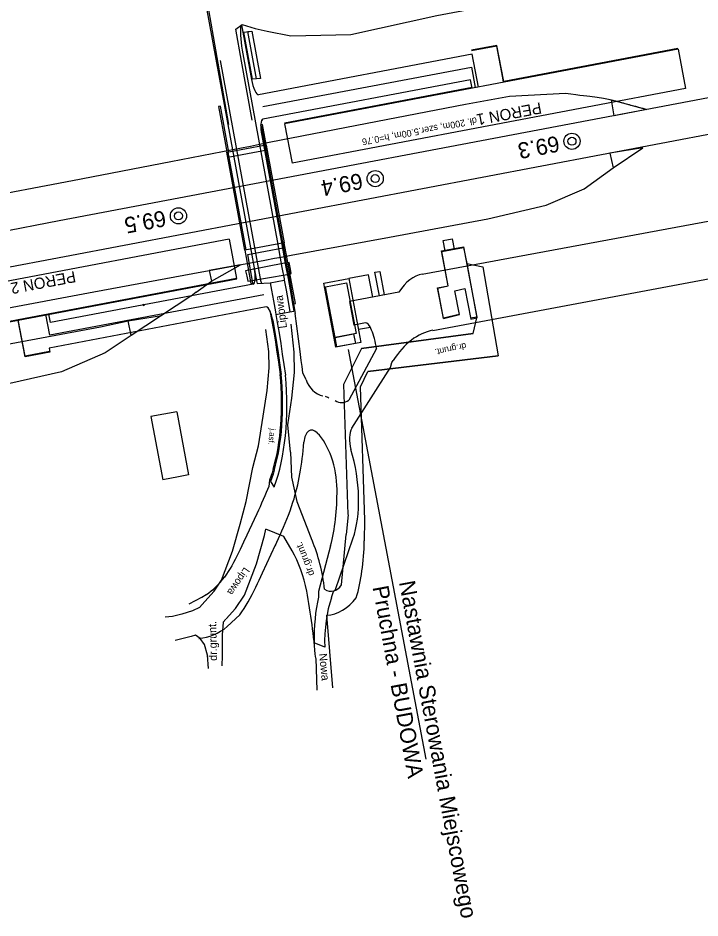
# Model space of a CAD drawing. Extents: x 6541740 to 6566395, y 5525066 to 5530361.
# Drawn here: x 6555216.3 to 6555301.5, y 5525704 to 5525816.3 of the extents above; entities that cross this region are included whole.
import ezdxf

# ---------------------------------------------------------------- set-up
doc = ezdxf.new("R2010")
doc.units = 0
for name, color, linetype in [('Domyślna', 7, 'Continuous'), ('ps_wymiarowanie', 7, 'Continuous'), ('TOR_PRZEK_P-komponent', 7, 'Continuous'), ('TOR_PRZEK_P-pomoc', 7, 'Continuous'), ('TOR_PS_OPIS_T-symbole geometrii', 7, 'Continuous'), ('TOR_PS_T-rowy otwarte nieumocnione', 7, 'Continuous'), ('TOR_PS_T-wypelnienia', 7, 'Continuous'), ('TOR_RAMKI-ramka+tabelka 1', 7, 'Continuous'), ('TOR_W-warstwa dodatkowa 2', 7, 'Continuous')]:
    doc.layers.add(name, color=color, linetype=linetype)

# ---------------------------------------------------------------- blocks, each defined once
blk = doc.blocks.new('4010_1')
at = {"layer": 'Domyślna'}
for radius in [0.75, 0.375]:
    blk.add_circle((0, 0), radius, dxfattribs=at)

msp = doc.modelspace()

# ---------------------------------------------------------------- linework, layer by layer
at = {"layer": 'ps_wymiarowanie'}
for p, q in [((6555269.64, 5525787.23), (6555269.4, 5525788.5)), ((6555269.19, 5525787.23), (6555271.94, 5525787.72)), ((6555270, 5525782.87), (6555269.19, 5525787.23)), ((6555271.94, 5525787.72), (6555273.59, 5525778.94)), ((6555268.7, 5525782.61), (6555270, 5525782.87)), ((6555269.42, 5525778.84), (6555268.7, 5525782.61)), ((6555269.43, 5525778.8), (6555268.71, 5525782.57)), ((6555271.38, 5525779.28), (6555269.42, 5525778.84)), ((6555273.59, 5525778.94), (6555272.81, 5525778.81)), ((6555236.12, 5525767.14), (6555232.91, 5525766.55)), ((6555236.12, 5525767.14), (6555237.61, 5525759.25)), ((6555232.91, 5525766.55), (6555234.41, 5525758.66))]:
    msp.add_line(p, q, dxfattribs=at)
msp.add_lwpolyline([(6555269.64, 5525787.23), (6555269.4, 5525788.5), (6555270.51, 5525788.71), (6555270.75, 5525787.44)], close=True, dxfattribs=at)
for points in [[(6555268.71, 5525782.57), (6555270.03, 5525782.87), (6555269.21, 5525787.15)], [(6555269.21, 5525787.15), (6555271.94, 5525787.66), (6555272.34, 5525785.65), (6555273.6, 5525778.86)], [(6555269.43, 5525778.8), (6555271.41, 5525779.26), (6555270.84, 5525782.24), (6555272.11, 5525782.53), (6555272.85, 5525778.68), (6555273.6, 5525778.86)], [(6555237.61, 5525759.25), (6555236.36, 5525759), (6555234.41, 5525758.66)]]:
    msp.add_lwpolyline(points, dxfattribs=at)
at = {"layer": 'TOR_PRZEK_P-komponent'}
for p, q in [((6555381.82, 5525821.35), (6555221.45, 5525790.95)), ((6555362.21, 5525813.05), (6555222.13, 5525786.49)), ((6555221.45, 5525790.95), (6555010.48, 5525750.96)), ((6555222.13, 5525786.49), (6554997.05, 5525743.82))]:
    msp.add_line(p, q, dxfattribs=at)
at = {"layer": 'TOR_PRZEK_P-pomoc'}
for p, q in [((6555298.72, 5525812.39), (6555249.59, 5525803.08)), ((6555298.7, 5525812.47), (6555276.95, 5525808.34)), ((6555298.72, 5525812.39), (6555299.65, 5525807.48)), ((6555273.01, 5525807.6), (6555249.58, 5525803.16)), ((6555299.65, 5525807.48), (6555250.52, 5525798.16)), ((6555249.59, 5525803.08), (6555250.52, 5525798.16)), ((6555242.67, 5525788.69), (6555193.54, 5525779.37)), ((6555242.67, 5525788.69), (6555243.6, 5525783.77)), ((6555243.62, 5525783.69), (6555216.34, 5525778.53)), ((6555243.6, 5525783.77), (6555216.35, 5525778.61)), ((6555216.35, 5525778.61), (6555194.48, 5525774.46)), ((6555216.34, 5525778.53), (6555194.49, 5525774.38))]:
    msp.add_line(p, q, dxfattribs=at)
at = {"layer": 'TOR_PS_OPIS_T-symbole geometrii'}
for p, q in [((6555244.22, 5525815.42), (6555245.46, 5525808.62)), ((6555244.37, 5525811.8), (6555248.74, 5525788.01)), ((6555241.55, 5525811), (6555245.84, 5525787.66)), ((6555246.66, 5525802.8), (6555249.36, 5525788.07)), ((6555246.75, 5525801.63), (6555249.24, 5525788.06)), ((6555266.79, 5525784.32), (6555310.58, 5525792.41)), ((6555268.12, 5525777.3), (6555307.72, 5525784.7)), ((6555247.81, 5525783.23), (6555249.55, 5525783.55)), ((6555246.15, 5525783.16), (6555247.81, 5525783.23)), ((6555263.87, 5525782.08), (6555257.69, 5525780.9)), ((6555257.69, 5525780.9), (6555258.25, 5525777.94)), ((6555248.5, 5525779.29), (6555250.25, 5525779.61)), ((6555250.25, 5525779.61), (6555250.74, 5525779.7)), ((6555259.71, 5525778.23), (6555258.25, 5525777.95)), ((6555262.98, 5525773.27), (6555263.15, 5525773.53)), ((6555257.99, 5525765.08), (6555262.81, 5525772.65)), ((6555262.81, 5525772.65), (6555262.98, 5525773.27)), ((6555247.72, 5525758.6), (6555247.61, 5525757.8)), ((6555247.84, 5525758.43), (6555248.3, 5525757.75)), ((6555246.11, 5525754.4), (6555244.55, 5525751.04)), ((6555255.96, 5525744.97), (6555258.13, 5525751.28)), ((6555255.32, 5525750.41), (6555253.82, 5525744.7)), ((6555239.27, 5525743.98), (6555239.82, 5525744.35)), ((6555253.82, 5525744.7), (6555253.82, 5525744.03)), ((6555255.43, 5525743.94), (6555255.7, 5525744.71)), ((6555255.7, 5525744.71), (6555255.96, 5525744.97)), ((6555239.22, 5525743.95), (6555237.62, 5525743.11)), ((6555244, 5525741.78), (6555242.44, 5525740.33)), ((6555254.6, 5525737.74), (6555253.28, 5525738.31))]:
    msp.add_line(p, q, dxfattribs=at)
for points in [[(6555232.86, 5525855.52), (6555232.99, 5525854.81), (6555233.25, 5525853.4), (6555233.51, 5525852), (6555233.51, 5525852), (6555241.02, 5525811.14), (6555245.34, 5525787.61)], [(6555249.25, 5525788.01), (6555249.5, 5525786.61), (6555249.76, 5525785.2), (6555250.02, 5525783.77), (6555250.28, 5525782.34), (6555250.54, 5525780.88), (6555250.74, 5525779.7)], [(6555249.37, 5525788.02), (6555249.63, 5525786.62), (6555249.89, 5525785.21), (6555250.15, 5525783.78), (6555250.41, 5525782.34), (6555250.67, 5525780.88), (6555250.92, 5525779.41)], [(6555245.34, 5525787.61), (6555245.59, 5525786.23), (6555245.85, 5525784.85), (6555246.09, 5525783.49), (6555246.15, 5525783.16)], [(6555245.84, 5525787.66), (6555246.09, 5525786.27), (6555246.35, 5525784.89), (6555246.6, 5525783.52), (6555246.72, 5525783.18)], [(6555248.75, 5525787.96), (6555249, 5525786.57), (6555249.26, 5525785.16), (6555249.52, 5525783.75), (6555249.55, 5525783.55)], [(6555249.55, 5525783.55), (6555249.77, 5525782.32), (6555250.03, 5525780.89), (6555250.25, 5525779.61)], [(6555247.81, 5525783.23), (6555247.97, 5525782.33), (6555248.21, 5525780.98), (6555248.45, 5525779.63), (6555248.5, 5525779.29)], [(6555247.73, 5525779.77), (6555248.13, 5525777.73), (6555248.24, 5525777.08), (6555248.44, 5525775.81), (6555248.64, 5525774.56), (6555248.83, 5525773.32), (6555249.05, 5525771.81)], [(6555248.5, 5525779.29), (6555248.67, 5525778.29), (6555248.9, 5525776.96), (6555249.11, 5525775.64), (6555249.31, 5525774.33), (6555249.51, 5525773.03), (6555249.7, 5525771.69)], [(6555252.27, 5525771.14), (6555251.85, 5525772.01), (6555251.77, 5525772.77), (6555251.68, 5525773.53), (6555251.58, 5525774.28), (6555251.52, 5525774.65), (6555250.92, 5525779.41)], [(6555248.12, 5525778.55), (6555248.37, 5525777.06), (6555248.58, 5525775.78), (6555248.78, 5525774.51), (6555248.96, 5525773.26), (6555249.18, 5525771.79)], [(6555261.08, 5525775.03), (6555257.6, 5525768.59)], [(6555248.18, 5525760.02), (6555248.03, 5525759.52), (6555247.88, 5525759.06), (6555247.72, 5525758.6)], [(6555248.3, 5525759.86), (6555248.15, 5525759.36), (6555248, 5525758.89), (6555247.84, 5525758.43)], [(6555247.61, 5525757.8), (6555247.31, 5525757.07), (6555247.12, 5525756.63), (6555246.93, 5525756.18), (6555246.73, 5525755.74), (6555246.53, 5525755.29), (6555246.32, 5525754.85), (6555246.11, 5525754.4)], [(6555244, 5525741.78), (6555244.27, 5525742.16), (6555244.54, 5525742.57), (6555244.8, 5525743), (6555245.05, 5525743.43), (6555245.3, 5525743.87), (6555245.54, 5525744.32), (6555245.77, 5525744.77), (6555245.99, 5525745.23), (6555246.21, 5525745.69), (6555246.43, 5525746.14), (6555246.64, 5525746.6), (6555246.85, 5525747.05), (6555246.85, 5525747.05), (6555248.46, 5525750.52), (6555248.41, 5525750.41), (6555248.62, 5525750.86), (6555248.84, 5525751.32), (6555249.05, 5525751.78), (6555249.26, 5525752.26), (6555249.47, 5525752.74), (6555249.68, 5525753.23), (6555249.88, 5525753.74), (6555250.08, 5525754.25), (6555250.28, 5525754.78), (6555250.47, 5525755.33), (6555250.64, 5525755.86)], [(6555244.68, 5525751.31), (6555244.47, 5525750.86), (6555244.26, 5525750.41), (6555244.05, 5525749.97), (6555243.84, 5525749.54), (6555243.64, 5525749.12), (6555243.43, 5525748.71), (6555243.21, 5525748.32), (6555243, 5525747.93), (6555242.78, 5525747.56), (6555242.56, 5525747.2), (6555242.34, 5525746.86), (6555242.1, 5525746.51)]]:
    msp.add_lwpolyline(points, dxfattribs=at)
for centre, major_axis, ratio, start_param, end_param in [((6555245.62, 5525811.92), (-0.93, 4.91), 0.25, 0.758321, 1.548465), ((6555245.96, 5525808.67), (0.37, -1.97), 0.25, 4.690058, 6.279955), ((6555247.24, 5525801.68), (-0.37, 1.97), 0.25, 6.279955, 7.831651), ((6555276.55, 5525732.74), (-9.78, 51.58), 0.25, 6.281998, 6.535305), ((6555247.67, 5525778.26), (-0.37, 1.97), 0.25, 4.81114, 6.283185), ((6555260.27, 5525775.28), (-0.56, 2.95), 0.25, 4.578281, 6.283592), ((6555272.54, 5525753.97), (-4.44, 23.33), 0.499999, 6.281393, 6.771299), ((6555237.67, 5525773.93), (-4.11, 21.59), 0.499999, 3.919278, 4.519453), ((6555237.67, 5525773.93), (-4.16, 21.83), 0.499999, 3.919278, 4.519453), ((6555237.67, 5525773.93), (-4.35, 22.81), 0.499999, 3.83349, 4.519453), ((6555254.88, 5525772.13), (-0.58, 3.05), 0.897189, 1.728216, 2.750899), ((6555254.48, 5525767.93), (-0.21, 1.1), 0.976601, 5.483546, 5.892492), ((6555256.72, 5525769.68), (-0.26, 1.38), 0.999987, 2.341953, 3.629706), ((6555253.32, 5525762.37), (-0.47, 2.46), 0.499999, 5.655689, 7.358003), ((6555252.79, 5525759.07), (-1.19, 6.26), 0.499999, 4.357266, 5.655689), ((6555258.93, 5525763.12), (-0.44, 2.33), 0.499999, 0.488113, 1.775866), ((6555237.67, 5525773.93), (-5.15, 27.04), 0.499999, 3.889479, 4.21641), ((6555252.79, 5525759.07), (-2.15, 11.3), 0.499999, 3.861049, 4.917459), ((6555245.76, 5525762.47), (-3.7, 19.4), 0.499999, 3.950241, 4.357266), ((6555233.72, 5525765.42), (-4.16, 21.83), 0.499999, 3.327431, 3.579278), ((6555261.82, 5525734.62), (-3.04, 15.96), 0.499999, 0.849414, 1.244004), ((6555261.82, 5525734.62), (-2.57, 13.51), 0.499999, 0.719457, 1.244004), ((6555234.67, 5525763.97), (4.77, -25.05), 0.499999, 6.240346, 6.537831)]:
    msp.add_ellipse(centre, major_axis=major_axis, ratio=ratio, start_param=start_param, end_param=end_param, dxfattribs=at)
at = {"layer": 'TOR_PS_T-rowy otwarte nieumocnione'}
for p, q in [((6555223.1, 5525796), (6555235.39, 5525798.36)), ((6555238.12, 5525784.38), (6555240.17, 5525784.76)), ((6555225.78, 5525782.1), (6555238.12, 5525784.38)), ((6555230.06, 5525778.47), (6555234.23, 5525779.15))]:
    msp.add_line(p, q, dxfattribs=at)
for points in [[(6555259.91, 5525803.17), (6555272.18, 5525805.55), (6555277.67, 5525806.54), (6555284.68, 5525806.91)], [(6555235.39, 5525798.36), (6555244.42, 5525800.13), (6555245.32, 5525800.3), (6555246.46, 5525800.54), (6555247.67, 5525800.77), (6555259.91, 5525803.17)], [(6555286.98, 5525794.96), (6555290.63, 5525797.58)], [(6555186.25, 5525789), (6555198.53, 5525791.32), (6555210.81, 5525793.69), (6555223.1, 5525796)], [(6555274.96, 5525791.23), (6555282.27, 5525792.91), (6555286.98, 5525794.96)], [(6555248.33, 5525786.3), (6555249.17, 5525786.45), (6555250.41, 5525786.68), (6555262.7, 5525788.95), (6555274.96, 5525791.23)], [(6555240.17, 5525784.76), (6555247.11, 5525786.06), (6555248.33, 5525786.3)], [(6555238.56, 5525782.05), (6555240.48, 5525783.43)], [(6555201.23, 5525777.46), (6555213.53, 5525779.81), (6555225.78, 5525782.1)], [(6555237.91, 5525781.58), (6555237.9, 5525781.58), (6555230.44, 5525776.64)], [(6555238.56, 5525782.05), (6555237.91, 5525781.58)], [(6555226.59, 5525777.74), (6555230.06, 5525778.47)], [(6555189.79, 5525770.76), (6555202.07, 5525773.1), (6555214.35, 5525775.45), (6555226.59, 5525777.73)], [(6555230.44, 5525776.64), (6555227.19, 5525774.5)], [(6555227.19, 5525774.5), (6555221.73, 5525772.13), (6555215.27, 5525770.65)]]:
    msp.add_lwpolyline(points, dxfattribs=at)
for points in [[(6555294.82, 5525804.88), (6555290.75, 5525804.08), (6555290.4, 5525806.06)], [(6555294.31, 5525800.08), (6555290.21, 5525799.4), (6555290.63, 5525797.58)], [(6555244.08, 5525785.49), (6555240.17, 5525784.76), (6555240.48, 5525783.43)], [(6555234.23, 5525779.15), (6555230.44, 5525776.64), (6555230.06, 5525778.47)]]:
    msp.add_lwpolyline(points, close=True, dxfattribs=at)
msp.add_open_spline([(6555284.68, 5525806.91), (6555286.58, 5525806.63), (6555288.47, 5525806.46), (6555290.4, 5525806.06), (6555291.13, 5525805.91), (6555291.87, 5525805.67), (6555292.61, 5525805.47), (6555293.35, 5525805.28), (6555294.09, 5525805.08), (6555294.82, 5525804.88)], degree=3, dxfattribs=at)
at = {"layer": 'TOR_PS_T-wypelnienia'}
for p, q in [((6555257.51, 5525754.28), (6555257.28, 5525751.84)), ((6555259.55, 5525751.02), (6555259.6, 5525753.59)), ((6555256.69, 5525745.56), (6555257.28, 5525751.84)), ((6555255.62, 5525732.67), (6555254.85, 5525741.75)), ((6555253.48, 5525736.36), (6555253.6, 5525732.4))]:
    msp.add_line(p, q, dxfattribs=at)
for points in [[(6555242.64, 5525802.98), (6555241.29, 5525810.65), (6555239.54, 5525820.69), (6555236.84, 5525835.55), (6555235.45, 5525843.55)], [(6555245.93, 5525814.97), (6555247.4, 5525814.66), (6555250.39, 5525814.05), (6555257.86, 5525814.24), (6555268.58, 5525816.61), (6555283.95, 5525819.5), (6555297.12, 5525822.42), (6555318.23, 5525825.3), (6555325.99, 5525826.63)], [(6555243.52, 5525814.89), (6555244.3, 5525815.48), (6555245.93, 5525814.97)], [(6555245.55, 5525803.54), (6555244.21, 5525810.91), (6555243.52, 5525814.89)], [(6555272.34, 5525785.65), (6555274.36, 5525785.21), (6555276.24, 5525774.13), (6555259.98, 5525772.15)], [(6555250.32, 5525762.1), (6555250.01, 5525765.52), (6555250.51, 5525768.85), (6555250.82, 5525772.05), (6555250.77, 5525774.58), (6555250.42, 5525778.08)], [(6555259.2, 5525775.04), (6555273.14, 5525776.89), (6555273.6, 5525778.86)], [(6555239.65, 5525743.48), (6555240.78, 5525744.75), (6555241.73, 5525746.14), (6555243.11, 5525749.73), (6555244.05, 5525753.13), (6555244.78, 5525755.94), (6555245.63, 5525760.19), (6555246.35, 5525762.88), (6555246.92, 5525766.58), (6555247.4, 5525769.8), (6555247.67, 5525772.64), (6555247.63, 5525774.66), (6555247.24, 5525777.41)], [(6555273.14, 5525776.89), (6555259.2, 5525775.04), (6555256.94, 5525770.53), (6555257.49, 5525754.3)], [(6555259.6, 5525753.59), (6555259.05, 5525770.25), (6555259.98, 5525772.15), (6555276.24, 5525774.13)], [(6555250.32, 5525762.1), (6555250.45, 5525758.97), (6555251.14, 5525755.95), (6555252.39, 5525752.72), (6555253.01, 5525751.1)], [(6555242.29, 5525741.28), (6555243.47, 5525742.6), (6555244.58, 5525744.23), (6555246.09, 5525748.15), (6555247.07, 5525751.7), (6555247.27, 5525752.48)], [(6555250.55, 5525749.79), (6555249.48, 5525751.59), (6555247.27, 5525752.48)], [(6555239.65, 5525743.48), (6555238.96, 5525742.73), (6555238.1, 5525742.3), (6555236.78, 5525741.89), (6555235.6, 5525741.6), (6555234.69, 5525741.52)], [(6555241.92, 5525740.87), (6555241.78, 5525739.29), (6555241.78, 5525736.67), (6555241.74, 5525735.41)], [(6555242.27, 5525741.26), (6555241.92, 5525740.87)], [(6555238.49, 5525739.26), (6555237.94, 5525739.09), (6555235.93, 5525738.6)], [(6555240.08, 5525735.1), (6555239.96, 5525736.76), (6555239.59, 5525738.1), (6555239.05, 5525738.86), (6555238.49, 5525739.26)]]:
    msp.add_lwpolyline(points, dxfattribs=at)
msp.add_lwpolyline([(6555249.96, 5525785.74), (6555249.59, 5525785.67), (6555244.7, 5525784.73), (6555244.87, 5525784.06), (6555245, 5525783.42), (6555249.93, 5525784.29), (6555250.43, 5525784.38), (6555250.32, 5525784.93), (6555250.16, 5525785.78)], close=True, dxfattribs=at)
for centre, major_axis, start_param, end_param in [((6555248.61, 5525745.6), (-2.18, 11.45), 4.564417, 5.116223), ((6555248.54, 5525757.26), (-3.92, 20.59), 3.916546, 4.310739), ((6555247.39, 5525743.45), (-1.92, 10.08), 4.747485, 5.293863), ((6555254.74, 5525749.54), (-0.91, 4.79), 2.71727, 3.641992), ((6555231.38, 5525741.24), (-7.96, 41.78), 4.50108, 4.701549), ((6555252.23, 5525758.51), (-3.18, 16.69), 3.075126, 3.562422)]:
    msp.add_ellipse(centre, major_axis=major_axis, ratio=0.499999, start_param=start_param, end_param=end_param, dxfattribs=at)
at = {"layer": 'TOR_W-warstwa dodatkowa 2'}
for p, q in [((6555249.39, 5525788.2), (6555247.15, 5525800.4)), ((6555249.57, 5525788.22), (6555247.32, 5525800.41)), ((6555244.62, 5525787.32), (6555242.38, 5525799.52)), ((6555244.8, 5525787.34), (6555242.56, 5525799.53)), ((6555260.06, 5525784.23), (6555257.6, 5525783.78)), ((6555260.61, 5525781.46), (6555260.06, 5525784.23)), ((6555217.2, 5525774.01), (6555216.34, 5525778.53)), ((6555217.21, 5525774.09), (6555216.35, 5525778.61)), ((6555260.3, 5525777.66), (6555258.81, 5525777.39)), ((6555220.28, 5525774.59), (6555217.2, 5525774.01)), ((6555220.26, 5525774.67), (6555217.21, 5525774.09)), ((6555257.53, 5525774.92), (6555267.23, 5525723.78))]:
    msp.add_line(p, q, dxfattribs=at)
for points in [[(6555246.58, 5525808.73), (6555245.59, 5525808.63), (6555244.5, 5525814.53), (6555245.5, 5525814.63)], [(6555246.58, 5525808.73), (6555246.09, 5525808.68), (6555245, 5525814.58), (6555245.5, 5525814.63)], [(6555260.88, 5525784.55), (6555261.47, 5525784.66), (6555262.02, 5525781.72), (6555261.43, 5525781.61)], [(6555254.49, 5525783.2), (6555257.6, 5525783.78), (6555259.11, 5525775.8), (6555256, 5525775.22)], [(6555258.52, 5525776.91), (6555255.9, 5525776.42), (6555254.7, 5525782.73), (6555257.33, 5525783.22)], [(6555255.9, 5525776.42), (6555258.21, 5525776.85), (6555258.44, 5525775.67), (6555256.12, 5525775.24)]]:
    msp.add_lwpolyline(points, close=True, dxfattribs=at)
for points in [[(6555276.95, 5525808.34), (6555276.09, 5525812.86), (6555272.91, 5525812.26)], [(6555276.83, 5525808.83), (6555276.09, 5525812.78), (6555272.93, 5525812.18)], [(6555273.79, 5525807.66), (6555273.01, 5525811.76), (6555246.33, 5525806.7)], [(6555246.89, 5525805.24), (6555272.92, 5525810.15), (6555273.4, 5525807.59)], [(6555273.02, 5525807.52), (6555272.82, 5525808.58), (6555246.87, 5525803.66)], [(6555276.94, 5525808.26), (6555276.83, 5525808.83)], [(6555247.06, 5525800.38), (6555242.64, 5525799.55), (6555241.6, 5525805.27), (6555241.35, 5525805.22), (6555242.49, 5525798.91), (6555247.43, 5525799.84), (6555246.85, 5525803.01), (6555246.6, 5525802.97), (6555246.6, 5525802.97), (6555247.06, 5525800.38)], [(6555245.64, 5525783.2), (6555245.64, 5525783.2), (6555245, 5525786.76), (6555249.42, 5525787.6), (6555250.68, 5525780.59), (6555250.94, 5525780.64), (6555249.56, 5525788.24), (6555244.63, 5525787.3), (6555245.38, 5525783.15), (6555245.64, 5525783.2)], [(6555245.69, 5525783.07), (6555220.37, 5525778.27), (6555220.17, 5525779.33)], [(6555247, 5525781.75), (6555220.28, 5525776.68), (6555219.79, 5525779.26)], [(6555247.3, 5525780.23), (6555220.18, 5525775.09), (6555220.28, 5525774.59)]]:
    msp.add_lwpolyline(points, dxfattribs=at)
for centre, major_axis, start_param, end_param in [((6555245.96, 5525808.67), (0.37, -1.97), 4.690058, 6.283185), ((6555247.24, 5525801.7), (-0.37, 1.97), 6.283185, 7.831651), ((6555245.31, 5525785.03), (-0.37, 1.97), 3.141593, 4.686711), ((6555247.67, 5525778.26), (-0.37, 1.97), 4.640081, 6.283185)]:
    msp.add_ellipse(centre, major_axis=major_axis, ratio=0.25, start_param=start_param, end_param=end_param, dxfattribs=at)
msp.add_ellipse((6555232, 5525780.47), major_axis=(-0.0186, 0.0983), ratio=0.25, dxfattribs=at)

# ---------------------------------------------------------------- block references
at = {"layer": 'TOR_RAMKI-ramka+tabelka 1', "xscale": 1.345963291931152, "yscale": 1.345963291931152}
for p in [(6555285.47, 5525800.9), (6555260.91, 5525796.24), (6555236.34, 5525791.59)]:
    msp.add_blockref('4010_1', p, dxfattribs=at)

# ---------------------------------------------------------------- texts
at = {"layer": 'TOR_PRZEK_P-pomoc'}
for s, height, rotation, p in [('PERON 1', 1.4, 190.7101, (6555281.53, 5525805.77)), ('dł. 200m, szer.5.00m, h=0.76', 0.84, 190.7075, (6555273.52, 5525803.91)), ('PERON 2', 1.4, 190.7101, (6555223.37, 5525784.72))]:
    msp.add_text(s, height=height, rotation=rotation, dxfattribs=at).set_placement(p)
at = {"layer": 'TOR_PS_T-wypelnienia'}
for s, height, rotation, p in [('Lipowa', 0.979, 97.6671, (6555249.9, 5525777.62)), ('dr.grunt.', 0.8, 191.9668, (6555272.19, 5525775.76)), ('j.asf.', 0.72, 262.8972, (6555247.79, 5525765.09)), ('dr.grunt.', 0.897, 111.7391, (6555253.35, 5525746.86)), ('Lipowa', 0.908, 235.4751, (6555244.57, 5525747.8)), ('dr.grunt.', 0.997, 91.2644, (6555241.16, 5525736.07)), ('Nowa', 0.999, 275.7493, (6555253.89, 5525736.94))]:
    msp.add_text(s, height=height, rotation=rotation, dxfattribs=at).set_placement(p)
at = {"layer": 'TOR_RAMKI-ramka+tabelka 1'}
for s, p in [('69.3', (6555283.7, 5525801.61)), ('69.4', (6555259.13, 5525796.95)), ('69.5', (6555234.57, 5525792.3))]:
    msp.add_text(s, height=2, rotation=190.7691, dxfattribs=at).set_placement(p)
at = {"layer": 'TOR_W-warstwa dodatkowa 2'}
for s, p in [('Pruchna - BUDOWA', (6555260.56, 5525745.25)), ('Nastawnia Sterowania Miejscowego', (6555263.87, 5525745.87))]:
    msp.add_text(s, height=2, rotation=280.5213, dxfattribs=at).set_placement(p)

doc.saveas('drawing.dxf')
